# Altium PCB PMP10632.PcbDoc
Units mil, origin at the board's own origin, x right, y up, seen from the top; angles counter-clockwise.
Board outline 3700 x 2300 mil, 2 copper layers (Top Layer, Bottom Layer), stack 62 mil thick; 85 components, 32 nets, 206 pads, 12 vias.
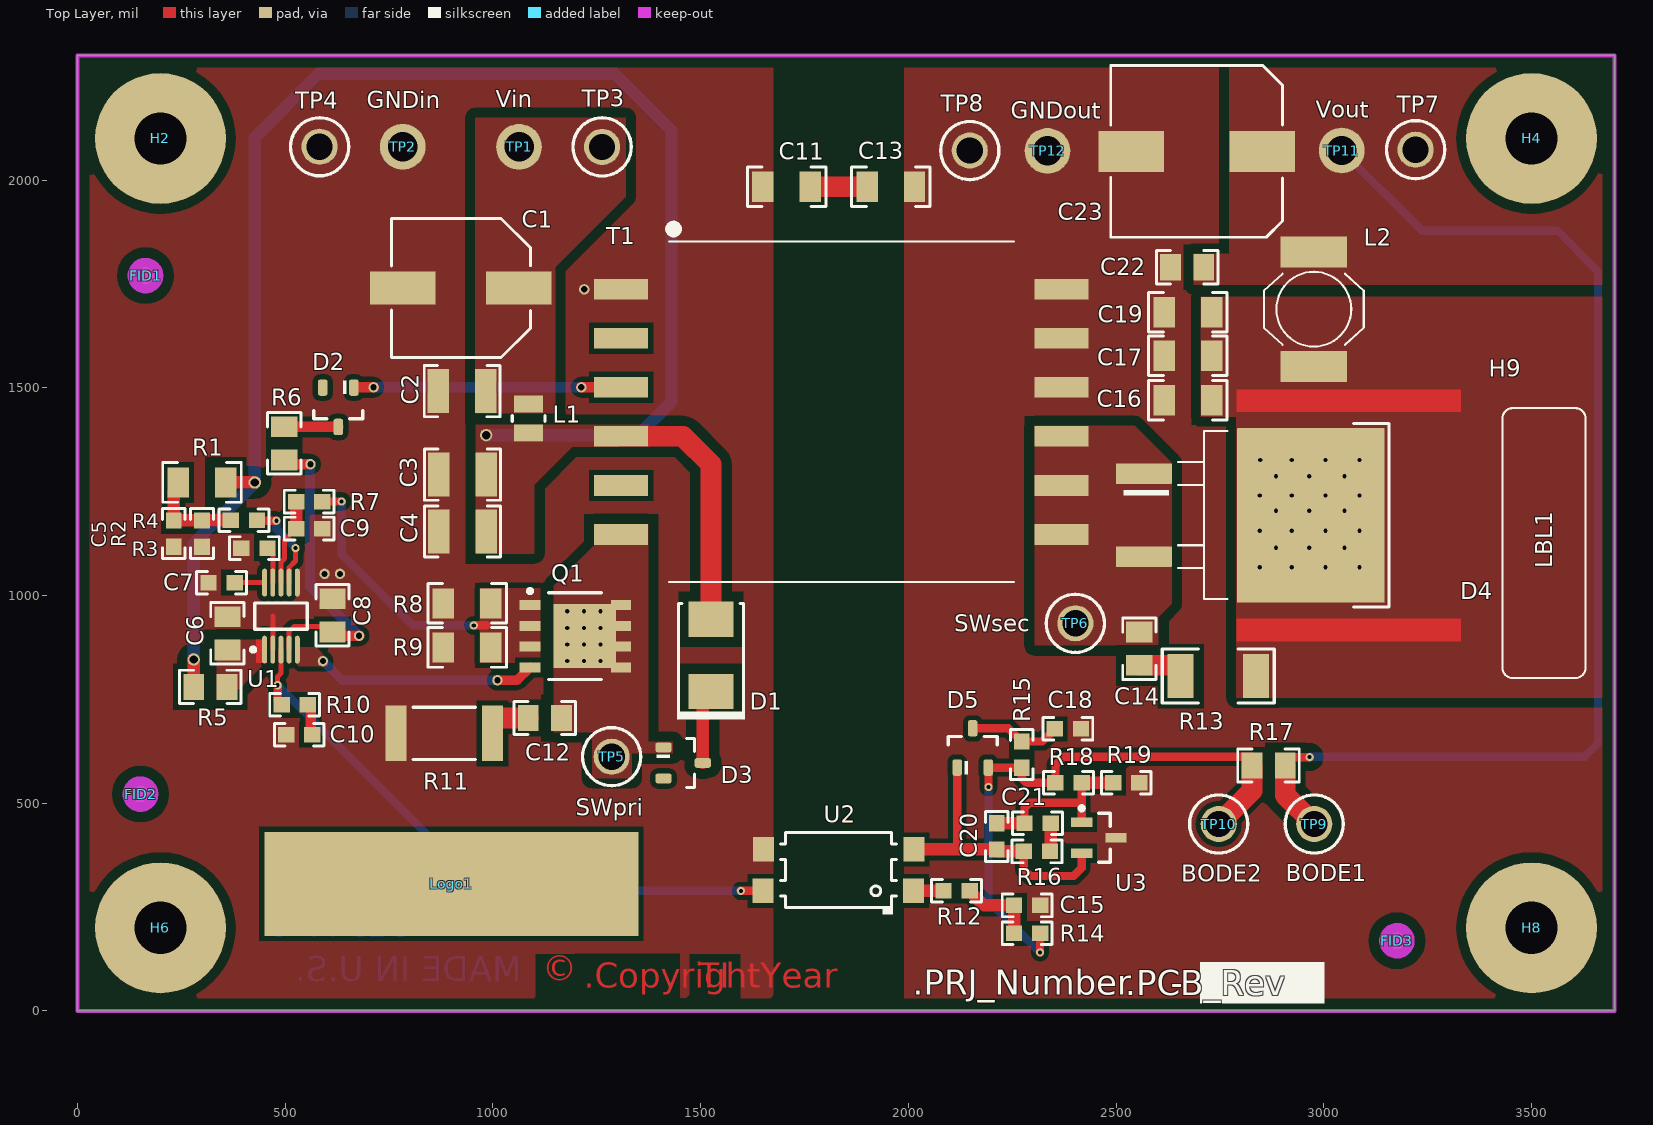
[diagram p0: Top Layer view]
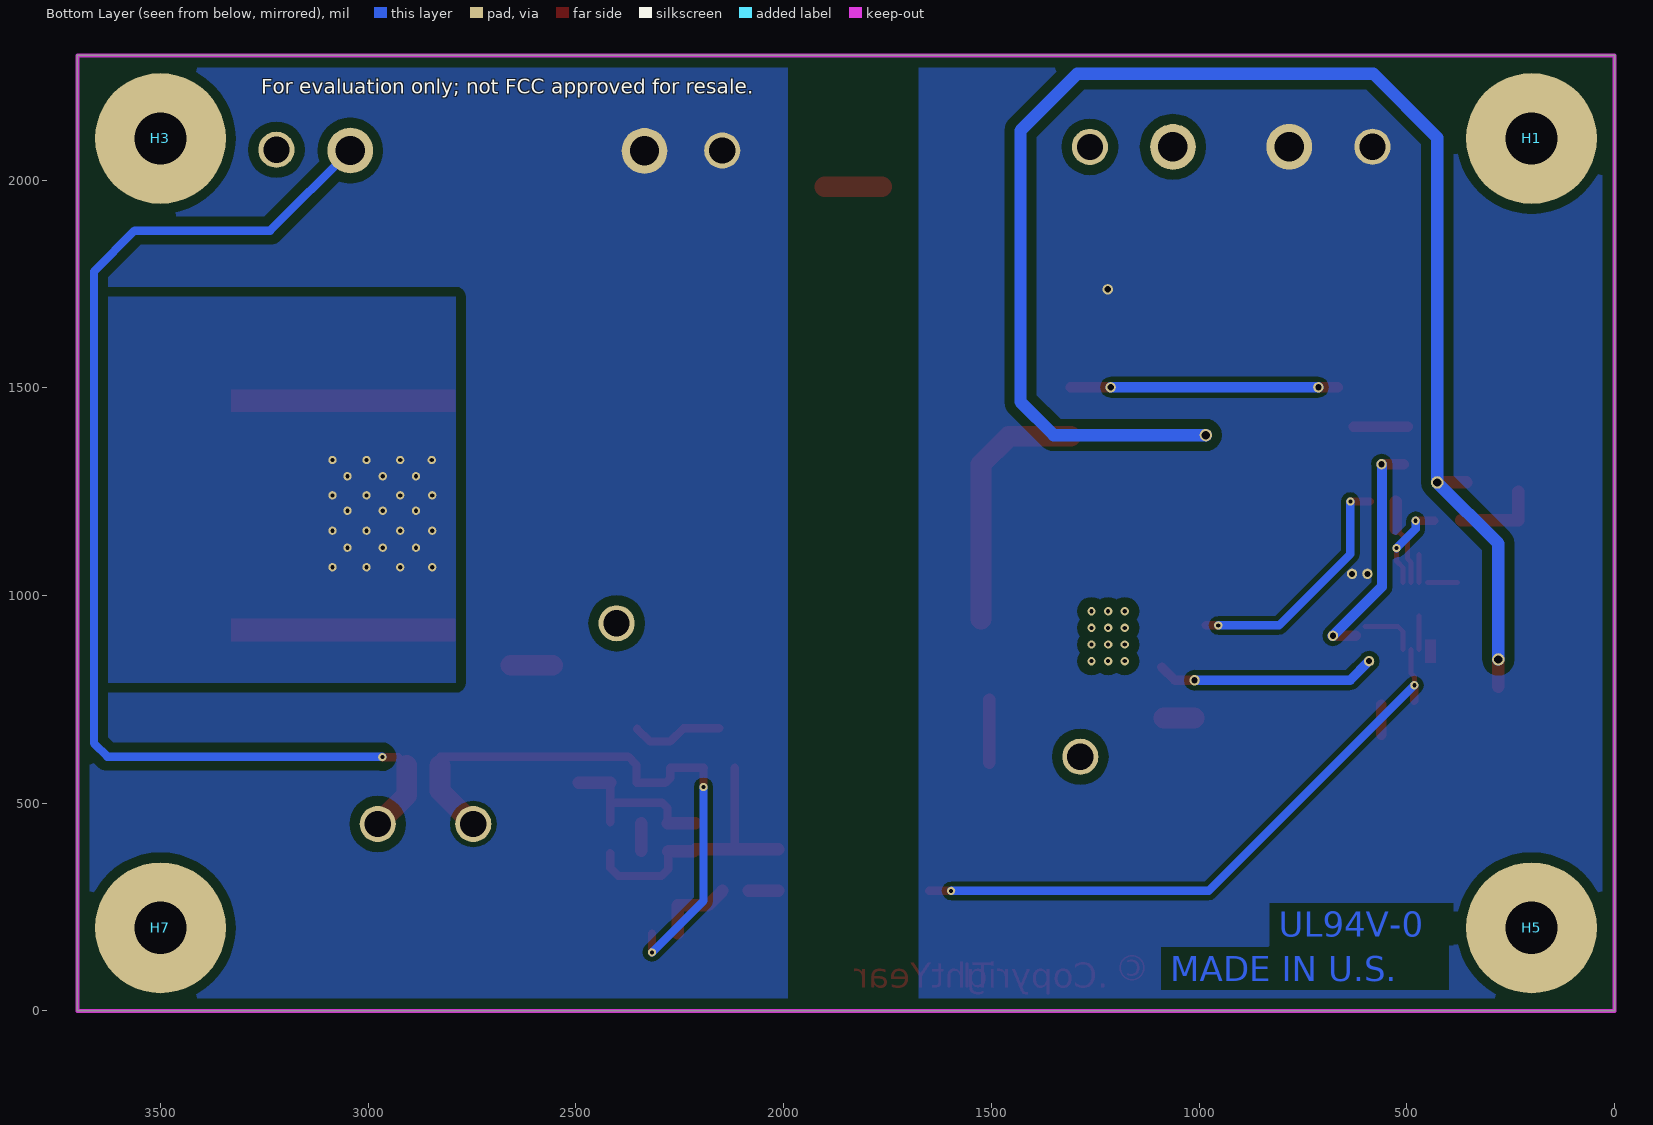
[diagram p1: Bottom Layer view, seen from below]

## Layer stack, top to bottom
Top Layer: signal copper 1.4
Dielectric: core 59.2, FR-4, Dk 4.8
Bottom Layer: signal copper 1.4

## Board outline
0,0 3700,0 3700,2300 0,2300

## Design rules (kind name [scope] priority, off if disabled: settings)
AcuteAngle [All] p1: minimum=4.50000000000000E+0001 checktracksonly=FALSE
AssemblyTestPointUsage [All] p1: valid=2
Clearance Clearance_PolygonandMountHole [InPolygon vs (InComponent('H1') OR InComponent('H2') OR InComponent('H3') OR InComponent('H4') OR InComponent('H5') OR InComponent('H6') OR InComponent('H7') OR InComponent('H8'))] p1: gap=24
Clearance Clearance_VinIC [InNet('VINIC')] p2: gap=24
Clearance Clearance_NoNet [InNet('No Net')] p3: gap=24
Clearance Clearance_SWpri [InNet('SWPRI')] p4: gap=24
Clearance Clearance_CLAMP [InNet('CLAMP')] p5: gap=24
Clearance Clearance_Vin [InNet('VIN')] p6: gap=24
Clearance Clearance_INPUT [InNet('INPUT')] p7: gap=24
Clearance Clearance_Vout [InNet('VOUT')] p8: gap=24
Clearance Clearance_VoutRect [InNet('VOUTRECT')] p9: gap=24
Clearance Clearance_SnubSec [InNet('SNUBSEC')] p10: gap=24
Clearance Clearance_SWsec [InNet('SWSEC')] p11: gap=24
Clearance Clearance_BoardEdge_MountingHoles [OnCopper and InComponentClass('Mounting Holes') vs IsKeepOut] p12: gap=30
Clearance Clearance_BoardEdge_Poly [OnCopper and InPoly vs IsKeepOut] p13: gap=25
Clearance Clearance_BoardEdge [OnCopper and Not InComponentClass('Logo') and not InComponentClass('FiducialMark') and not InRegion(1000,500,4000,800) and Not IsKeepout vs IsKeepOut] p14: gap=25
Clearance Clearance_Poly [InPolygon] p15: gap=12
Clearance [All] p16: gap=10
ComponentClearance ComponentClearance_Shunt [InComponentClass('Header') vs InComponentClass('Shunt')] p1: gap=0 collisioncheckmode=3 verticalgap=0 showdistances=FALSE
ComponentClearance ComponentClearance_MountingHoles_FiducialMarks [InComponentClass('Mounting Holes') vs InComponentClass('FiducialMark')] p2: gap=30 collisioncheckmode=3 verticalgap=10 showdistances=FALSE
ComponentClearance ComponentClearance_Logo [InComponentClass('Logo')] p3: gap=30 collisioncheckmode=3 verticalgap=10 showdistances=FALSE
ComponentClearance ComponentClearance_ScrewToNut [(HasFootprint('NY PMS 440 0025 PH')) vs (HasFootprint('Keystone_1902C'))] p4: gap=5 collisioncheckmode=3 verticalgap=10 showdistances=FALSE
ComponentClearance ComponentClearance_MountingHoles [InComponentClass('Mounting Holes')] p5: gap=30 collisioncheckmode=3 verticalgap=100000 showdistances=FALSE
ComponentClearance ComponentClearance_SmallPassives [HasFootprint('0201*') or HasFootprint('0402*') or HasFootprint('0508') or HasFootprint('0603*') or HasFootprint('0612') or HasFootprint('0805*') or HasFootprint('0815*') or HasFootprint('0830*') or HasFootprint('1206*') or HasFootprint('1210*') or HasFootprint('1808*') or HasFootprint('1812*') or HasFootprint('1825*') or HasFootprint('2010*') or HasFootprint('2220*') or HasFootprint('2225*') or HasFootprint('2512*') or HasFootprint('2728*') or HasFootprint('3518*') vs HasFootprint('0201*') or HasFootprint('0402*') or HasFootprint('0508') or HasFootprint('0603*') or HasFootprint('0612') or HasFootprint('0805*') or HasFootprint('0815*') or HasFootprint('0830*') or HasFootprint('1206*') or HasFootprint('1210*') or HasFootprint('1808*') or HasFootprint('1812*') or HasFootprint('1825*') or HasFootprint('2010*') or HasFootprint('2220*') or HasFootprint('2225*') or HasFootprint('2512*') or HasFootprint('2728*') or HasFootprint('3518*')] p6: gap=20 collisioncheckmode=3 verticalgap=10 showdistances=FALSE
ComponentClearance ComponentClearance_THtoSMT [IsThruComponent vs IsSMTComponent] p7: gap=30 collisioncheckmode=3 verticalgap=30 showdistances=FALSE
ComponentClearance ComponentClearance_THtoTH [IsThruComponent vs IsThruComponent] p8: gap=30 collisioncheckmode=3 verticalgap=30 showdistances=FALSE
ComponentClearance [All] p9: gap=15 collisioncheckmode=3 verticalgap=10 showdistances=FALSE
DiffPairsRouting [All] p1: maxlimit=100 minlimit=10 mostfreqgap=10 maxuncoupledlength=1000
FabricationTestPointUsage TestPointUsage [All] p1: valid=2 allowmultiple=FALSE
FabricationTestpoint Testpoint [All] p1: side=3 testpointundercomponent=TRUE minsize=40 maxsize=100 preferedsize=60 minholesize=0 maxholesize=40 preferedholesize=32 testpointgrid=1 allowsidetop=TRUE allowsidebottom=TRUE usegrid=TRUE gridtolerance=0.01
FanoutControl Fanout_LCC [IsLCC] p1: bgadir=Out bgaviamode=Centered fanoutstyle=Auto fanoutdirection=Alternating viagrid=1 // Fanout_LCC (Default Rule)
FanoutControl Fanout_BGA [IsBGA] p2: bgadir=Out bgaviamode=Centered fanoutstyle=Auto fanoutdirection=Alternating viagrid=1 // Fanout_BGA (Default Rule)
FanoutControl Fanout_Default [All] p4: bgadir=Out bgaviamode=Centered fanoutstyle=Auto fanoutdirection=Alternating viagrid=1 // Fanout_Default (Default Rule)
FanoutControl Fanout_Small [(CompPinCount < 5)] p5: bgadir=Out bgaviamode=Centered fanoutstyle=Auto fanoutdirection=OutThenIn viagrid=1 // Fanout_Small (Default Rule)
HoleSize [All] p1: absolutevalues=TRUE maxlimit=251 minlimit=10 maxpercent=80.000 minpercent=20.000
MinimumAnnularRing MinimumAnnularRing_ThermalPadVias [IsVia and InAnyComponent] p1: minimumring=5
MinimumAnnularRing [All] p2: minimumring=5
MinimumSolderMaskSliver MinimumSolderMaskSliver_Logo [InComponentClass('Logo') vs InComponentClass('Logo')] p1: minsoldermaskwidth=0.7
MinimumSolderMaskSliver [All] p2: minsoldermaskwidth=3.94
PlaneConnect [All] p1: planeconnectstyle=Direct reliefexpansion=10 reliefentries=4 reliefconductorwidth=10 reliefairgap=10
PolygonConnect [All] p1: connectstyle=Direct reliefconductorwidth=10 reliefentries=4 polygonreliefangle="90 Angle" airgapwidth=10
RoutingVias ThermalPadVias [IsVia and InAnyComponent] p1: holewidth=7.87 width=19.68 viastyle="Through Hole" minholewidth=10 minwidth=19.68 maxholewidth=12.99 maxwidth=23.62
RoutingVias [All] p2: holewidth=16 width=34 viastyle="Through Hole" minholewidth=10 minwidth=20 maxholewidth=40 maxwidth=65
SMDToCorner [All] p1: distance=30000
SilkToSilkClearance SilkToSilkClearance_Pb-FreeLogo [(HasFootprint('Pb-Free_Overlay_Medium') OR HasFootprint('Pb-Free_Overlay_Small')) vs (HasFootprint('Pb-Free_Overlay_Medium') OR HasFootprint('Pb-Free_Overlay_Small'))] p1: silktosilkclearance=0
SilkToSilkClearance [All] p2: silktosilkclearance=5
SilkscreenOverComponentPads [All] p1: minsilkscreentomaskgap=5
SolderMaskExpansion [All] p1: expansion=1.97
Width [All] p1: maxlimit=100 minlimit=6 preferedwidth=10 checkconnectedcopper=TRUE
14 further rules are at their usual default settings.

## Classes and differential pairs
component class "PMP10632 Schematic": C1 C2 C3 C4 C5 C6 C7 C8 C9 C10 C11 C12 C13 C14 C15 C16 C17 C18 C19 C20 C21 C22 C23 D1 D2 D3 D4 D5 H9 L1 L2 Q1 R1 R2 R3 R4 R5 R6 R7 R8 R9 R10 R11 R12 R13 R14 R15 R16 R17 R18 R19 T1 TP1 TP2 TP3 TP4 TP5 TP6 TP7 TP8 TP9 TP10 TP11 TP12 U1 U2 U3
component class "Mounting Holes": H2 H4 H6 H8
component class Logo: Logo1
component class PMP10632_Hardware_ANSI-B: FID1 FID2 FID3 H1 H2 H3 H4 H5 H6 H7 H8 LBL1 Logo1 Logo3 ZZ1 ZZ2 ZZ3 ZZ4
component class FiducialMark: FID1 FID2 FID3
component class AssemblyNote: ZZ1 ZZ2 ZZ3 ZZ4
component class Label: LBL1

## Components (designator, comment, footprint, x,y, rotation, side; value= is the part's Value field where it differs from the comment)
C1 "EEE-FK2A220P" SM_RADIAL_F 923,1740 r180 top
C2 "GRM32ER72A225KA35L" 1210 926,1492 r180 top
C3 "GRM32ER72A225KA35L" 1210 927,1291 r180 top
C4 "GRM32ER72A225KA35L" 1210 927,1154 r180 top
C5 "GRM188R71E103KA01D" 0603 232,1149 r270 top
C6 "C0805C104K1RACTU" 0805_HV 361,909 r90 top
C7 "GRM188R71E103KA01D" 0603 347,1031 r180 top
C8 "GRM21BR71C475KA73L" 0805_HV 614,952 r90 top
C9 "C0603C102J5GAC" 0603 558,1161 r0 top
C10 "GRM188R71H223KA01D" 0603 534,665 r180 top
C11 "VJ1206Y222KXGAT5Z" 1206 1707,1984 r180 top
C12 "GRM2165C2A471JA01D" 0805_HV 1125,705 r180 top
C13 "VJ1206Y222KXGAT5Z" 1206 1958,1984 r180 top
C14 "GRM2165C2A471JA01D" 0805_HV 2556,872 r270 top
C15 "GRM188R71E104KA01D" 0603 2286,254 r0 top
C16 "GRM31CR71E106KA12L" 1206 2673,1470 r180 top
C17 "GRM31CR71E106KA12L" 1206 2673,1577 r180 top
C18 "GRM188R71A105KA61D" 0603 2384,679 r0 top
C19 "GRM31CR71E106KA12L" 1206 2673,1682 r180 top
C20 "DNP" 0603 2212.56,420 r270 top
C21 "GRM188R71H223KA01D" 0603 2311,452 r180 top
C22 "GRM219R71E105KA88D" 0805_HV 2671,1790 r180 top
C23 "UCL1V391MNL1GS" SM_RADIAL_10BMM 2694,2069 r180 top
D1 "1SMB5936BT3G" SMB 1525,856 r90 top
D2 "BAS21-7-F" SOT-23 628,1453 r270 top
D3 "BAS21-7-F" SOT-23 1458,597 r0 top
D4 "MBRB2535CTLT4G" DDPAK 2813,1193 r0 top
D5 "BAT54S-7-F" SOT-23 2155,633 r90 top
FID1 "Fiducial" Fiducial10-20 164,1770 r0 top
FID2 "Fiducial" Fiducial10-20 152,522 r0 top
FID3 "Fiducial" Fiducial10-20 3176,169 r0 top
H1 "1902C" Keystone_1902C 200,2100 r180 bottom locked
H2 "NY PMS 440 0025 PH" "NY PMS 440 0025 PH" 200,2100 r0 top locked
H3 "1902C" Keystone_1902C 3500,2100 r180 bottom locked
H4 "NY PMS 440 0025 PH" "NY PMS 440 0025 PH" 3500,2100 r0 top locked
H5 "1902C" Keystone_1902C 200,200 r180 bottom locked
H6 "NY PMS 440 0025 PH" "NY PMS 440 0025 PH" 200,200 r0 top locked
H7 "1902C" Keystone_1902C 3500,200 r180 bottom locked
H8 "NY PMS 440 0025 PH" "NY PMS 440 0025 PH" 3500,200 r0 top locked
H9 "573300D00010G" HEATSINK_573300D00010G 3060,1193 r90 top
L1 "PFL2010-471MEB" PFL2010 1086,1426 r270 top
L2 "DO1813H-181MLB" DO1813H 2976,1689 r90 top
LBL1 "Size: 0.65\" x 0.20 \"" Label_650x200 3530,1126 r90 top
Logo1 "Texas Instruments" TI_Stacked_SolderMask_Small 900,306 r0 top
Logo3 "FCC disclaimer" FCC_disclaimer 3598.2,3140 r180 bottom
Q1 "SI7898DP-E3" PowerPAK_SO-8 1199,902 r0 top
R1 "CRCW120661K9FKEA" 1206 300,1272 r0 top
R2 "CRCW06032K87FKEA" 0603 300,1149 r90 top
R3 "CRCW060312K4FKEA" 0603 426,1114 r0 top
R4 "CRCW06031K00FKEA" 0603 401,1181 r0 top
R5 "CRCW080510R0JNEA" 0805_HV 320,780 r180 top
R6 "CRCW080520R0JNEA" 0805_HV 498,1366 r270 top
R7 "CRCW0603100RFKEA" 0603 558,1226 r0 top
R8 "ERJ-8RQFR47V" 1206 938,981 r0 top
R9 "ERJ-8RQFR47V" 1206 938,875 r0 top
R10 "CRCW0603220RJNEA" 0603 523,737 r180 top
R11 "CRCW251210R0JNEG" 2512 883,668 r0 top
R12 "CRCW0603680RJNEA" 0603 2116,289 r0 top
R13 "CRCW201010R0FKEF" 2010 2746,806 r180 top
R14 "CRCW060310R0FKEA" 0603 2286,187 r180 top
R15 "CRCW060310K0JNEA" 0603 2273,617 r270 top
R16 "CRCW06031R00JNEA" 0603 2309.56,384 r180 top
R17 "CRCW080510R0JNEA" 0805_HV 2867,591 r0 top
R18 "CRCW060314K7FKEA" 0603 2385.56,549 r180 top
R19 "CRCW06038K87FKEA" 0603 2524.56,549 r180 top
T1 "B0695-A" B0695-A 1839,1442 r0 top
TP1 "Vin" Keystone1593-2 1063.05,2079.68 r270 top
TP2 "GNDin" Keystone1593-2 783,2079.97 r270 top
TP3 "" Keystone5010 1263.05,2079.68 r0 top
TP4 "" Keystone5011 583,2079.97 r0 top
TP5 "SWpri" Keystone5012 1286,612 r0 top
TP6 "SWsec" Keystone5012 2402,933 r0 top
TP7 "" Keystone5010 3221,2073 r0 top
TP8 "" Keystone5011 2148,2071 r0 top
TP9 "BODE1" Keystone5012 2977,450 r0 top
TP10 "BODE2" Keystone5012 2747,450 r0 top
TP11 "Vout" Keystone1593-2 3043,2071 r0 top
TP12 "GNDout" Keystone1593-2 2335,2070 r0 top
U1 "LM5020MM-1/NOPB" MUB10A_N 490,950.5 r90 top
U2 "FOD817ASD" N04C 1832,339 r180 top
U3 "LMV431AIMF" MF03A_N 2458.56,417 r0 top
ZZ1 "This Assembly Note is for PCB labels only" AssemblyNoteLabel -415,3738 r0 top
ZZ2 "These assemblies are ESD sensitive, ESD precautions shall be observed." AssemblyNote -415,3629.11 r0 top
ZZ3 "These assemblies must be clean and free from flux and all contaminants. Use of no clean flux is not acceptable." AssemblyNote -415,3540.56 r0 top
ZZ4 "These assemblies must comply with workmanship standards IPC-A-610 Class 2, unless otherwise specified." AssemblyNote -415,3452 r0 top

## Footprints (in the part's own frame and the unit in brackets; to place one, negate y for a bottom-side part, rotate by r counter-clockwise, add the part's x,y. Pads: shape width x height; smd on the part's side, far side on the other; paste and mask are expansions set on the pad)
0603 [mm] "0603 from SM-752 data"
  rect 1x0.95 smd: 1(-0.8,0) 2(0.8,0)
  silkscreen extent -1.52,-0.69 1.52,0.69, body extent -0.87,-0.47 0.87,0.47, height 0.85
0805_HV [mil] "0805 with 30mil clearance between pads"
  rect 50x63 smd: 1(-40,0) 2(40,0)
  silkscreen extent -74,-40 74,40, body extent -43,-29 43,29, height 43
1206 [mm] "1206 from SM-752 data"
  rect 1.3x1.85 smd: 1(-1.45,0) 2(1.45,0)
  silkscreen extent -2.4,-1.21 2.4,1.21, body extent -1.7,-0.9 1.7,0.9, height 1.35
1210 [mm] "1210 from SM-752 data"
  rect 1.3x2.7 smd: 1(-1.45,0) 2(1.45,0)
  silkscreen extent -2.32,-1.57 2.32,1.57, body extent -1.7,-1.35 1.7,1.35, height 1.35
2010 [mm] "Chip Capacitor, Body 5.08x2.54mm, IPC Medium Density"
  rect 1.6x2.7 smd: 1(-2.3,0) 2(2.3,0)
  silkscreen extent -3.42,-1.65 3.42,1.65, body extent -2.73,-1.45 2.73,1.45, height 1.66
2512 [mm] "Chip Resistor, Body 6.3x3.2mm, IPC Medium Density"
  rect 1.3x3.4 smd: 1(-2.95,0) 2(2.95,0)
  silkscreen extent -1.9,-1.6 1.9,1.6, body extent -3.22,-1.67 3.22,1.67, height 0.71
AssemblyNote [mil] "Assembly Note"
AssemblyNoteLabel [mil] "Assembly Note for PCB Labels"
B0695-A [mil] "1:0.23 and 1:0.69 Transformer"
  rect 130x50 smd: 1(-530,295) 2(-530,177) 3(-530,59) 4(-530,-59) 5(-530,-177) 6(-530,-295) 7(530,-295) 8(530,-177) 9(530,-59) 10(530,59) 11(530,177) 12(530,295)
  silkscreen extent -415,-410 415,450
DDPAK [mil] "D2-PAK, 3-Pads, Body 9.7x10.4mm (max), TO-263AB, using Vishay Silionix recommended pad sizes"
  rrect8% 135x49.49 smd: 1(-246.06,100) 3(-246.06,-100)
  rrect1% 355x420 smd paste-181.1: 4(155.51,0)
  silkscreen extent -295,-220 344,220, body extent -295,-202 324,202, height 180
DO1813H [mil] "Coilcraft DO1813H recommended land pattern"
  rect 75x160 smd: 1(-137.5,0) 2(137.5,0)
  silkscreen extent -90,-120 90,120, body extent -175,-120 175,120, height 197
FCC_disclaimer [mil]
Fiducial10-20 [mm]
  round 1 smd mask+0.5: 1(0,0)
  Top Layer keep-out circle w1.178: c0,0 r0.5
HEATSINK_573300D00010G [mil] "Aavid"
  Top Layer region: -248.03,269.68 -303.15,269.68 -303.15,-269.69 -248.03,-269.69
  Top Layer region: 248.03,-269.69 303.15,-269.69 303.15,269.68 248.03,269.68
  body extent -515,-250 515,250, height 400
Keystone1593-2 [mm] "Keystone Dual Turret"
  round 2.8 hole 1.8: 1(0,0)
  body extent -1.17,-1.19 1.21,1.19, height 4
Keystone5010 [mil] "Keystone Multipurpose loops"
  round 87 hole 63: 1(0,0)
  silkscreen extent -70,-70 70,70, body extent -63,-63 63,62, height 319
Keystone5011 [mil] "Keystone Multipurpose loops"
  round 87 hole 63: 1(0,0)
  silkscreen extent -70,-70 70,70, body extent -63,-63 63,62, height 319
Keystone5012 [mil] "Keystone Multipurpose loops"
  round 87 hole 63: 1(0,0)
  silkscreen extent -70,-70 70,70, body extent -63,-63 63,62, height 319
Keystone_1902C [mil] "Hex Standoff, 4-40 threaded, nylon"
  body extent -145,-126 146,126, height 501
Label_650x200 [mil] "Thermal Transfer Label"
  silkscreen extent -325,-100 325,100, body extent -326,-101 326,101, height 1
MF03A_N [mm] "SOT23, 3-Leads, Body 2.9x1.3mm, Pitch 0.95mm, Lead Span 2.4mm, IPC Medium Density"
  rect 1.3x0.6 smd: 1(-1.05,0.95) 2(-1.05,-0.95) 3(1.05,0)
  silkscreen extent -1.17,-1.5 0.7,1.92, body extent -0.7,-1.5 0.7,1.5, height 1.12
MUB10A_N [mm] "TSSOP, 10-Leads, Body 3x3mm, Pitch 0.5mm, IPC Medium Density"
  oval 1.7x0.3 smd: 1(-2.05,1) 2(-2.05,0.5) 3(-2.05,0) 4(-2.05,-0.5) 5(-2.05,-1) 6(2.05,-1) 7(2.05,-0.5) 8(2.05,0) 9(2.05,0.5) 10(2.05,1)
  silkscreen extent -2.17,-1.6 0.8,1.82, body extent -1.6,-1.6 1.6,1.6, height 1.09
N04C [mm] "FAIRCHILD"
  rect 1.3x1.5 smd mask+0.065: 1(-4.587,1.27) 2(-4.612,-1.27) 3(4.588,-1.27) 4(4.613,1.27)
  silkscreen extent -3.56,-2.3 3.56,2.72, body extent -5.08,-2.3 5.08,2.3, height 3.87
"NY PMS 440 0025 PH" [mm] "4-40 nylon screw and mounting hole"
  round 8 hole 3.2: 1(0,0)
  body extent -3.3,-3.3 3.3,3.3, height 2.69
PFL2010 [mm] "SMD, 2-Leads, Body 2.2x1.45mm"
  rect 1.02x1.78 smd: 1(-0.89,0) 2(0.89,0)
  silkscreen extent -0.18,-1 0.18,1, body extent -1.1,-0.72 1.1,0.73, height 0.99
PowerPAK_SO-8 [mil] "Vishay PowerPAK SO-8, Body 5.3x6.0mm (max), Pitch 1.27mm, IPC Medium Density"
  rect 50x24 smd mask+2.99: 1(-109.5,75) 2(-109.5,25) 3(-109.5,-25) 4(-109.5,-75)
  rect 48x24 smd mask+2.99: 5(109.5,-75) 8(109.5,75)
  rect 48x24 smd paste-12 mask+2.99: 6(109.5,-25) 7(109.5,25)
  rect 150x154 smd paste-75 mask+2.99: 9(22.5,0)
  silkscreen extent -114,-104 62,113, body extent -121,-102 121,102, height 43
SM_RADIAL_10BMM [mm] "Nichicon 10x10"
  rect 4x2.5 smd: 1(-4,0) 2(4,0)
  silkscreen extent -5.25,-5.25 5.25,5.25, body extent -5.26,-5.26 5.26,5.26, height 10.5
SM_RADIAL_F [mm] "8 x 10.2mm:  Panasonic F"
  rect 4x2 smd: 1(-3.55,0) 2(3.55,0)
  silkscreen extent -4.25,-4.25 4.25,4.25, body extent -4.26,-4.26 4.26,4.26, height 10.5
SMB [mil] "Molded Diode, 2-Leads, Body 5.4x3.6mm, IPC Medium Density, based on OnSemi component dimensions"
  rect 85x107.99 smd: 1(-87.01,0) 2(87.01,0)
  silkscreen extent -155,-82 125,82, body extent -106,-71 106,71, height 91
SOT-23 [mm] "SOT23, 3-Leads, Body 2.9x1.3mm, Pitch 0.95mm, Lead Span 2.5mm, IPC Medium Density"
  rrect50% 1x0.6 smd: 1(-1.2,0.95) 2(-1.2,-0.95) 3(1.2,0)
  silkscreen extent -1.63,-1.5 0.7,1.5, body extent -1.16,-1.45 1.21,1.45, height 1
TI_Stacked_SolderMask_Small [mil]
  rect 900x250 smd paste-125 mask-125: 0(0,0)

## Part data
C1: "CAP, AL, 22 µF, 100 V, +/- 20%, 1.3 ohm, SMD"
C2 C3 C4: "CAP, CERM, 2.2 µF, 100 V, +/- 10%, X7R, 1210"
C5 C7: "CAP, CERM, 0.01 µF, 25 V, +/- 10%, X7R, 0603"
C6: "CAP, CERM, 0.1 µF, 100 V, +/- 10%, X7R, 0805"
C8: "CAP, CERM, 4.7 µF, 16 V, +/- 10%, X7R, 0805"
C9: "CAP, CERM, 1000 pF, 50 V, +/- 5%, C0G/NP0, 0603"
C10 C21: "CAP, CERM, 0.022 µF, 50 V, +/- 10%, X7R, 0603"
C11 C13: "CAP, CERM, 2200 pF, 1000 V, +/- 10%, X7R, 1206"
C12 C14: "CAP, CERM, 470 pF, 100 V, +/- 5%, C0G/NP0, 0805"
C15: "CAP, CERM, 0.1 µF, 25 V, +/- 10%, X7R, 0603"
C16 C17 C19: "CAP, CERM, 10 µF, 25 V, +/- 10%, X7R, 1206"
C18: "CAP, CERM, 1 µF, 10 V, +/- 10%, X7R, 0603"
C20: library part GRM1885C1H101JA01D, "CAP, CERM, 100 pF, 50 V, +/- 5%, C0G/NP0, 0603"
C22: "CAP, CERM, 1 µF, 25 V, +/- 10%, X7R, 0805"
C23: "CAP, AL, 390 µF, 35 V, +/- 20%, 0.08 ohm, SMD"
D1: "Diode, Zener, 30 V, 550 mW, SMB"
D2 D3: "Diode, Switching, 200 V, 0.2 A, SOT-23"
D4: "Diode, Schottky, 35 V, 25 A, DDPAK"
D5: "Diode, Schottky, 30 V, 0.2 A, SOT-23"
FID1 FID2 FID3: "Fiducial mark.  There is nothing to buy or mount."
H1 H3 H5 H7: "Standoff, Hex, 0.5\"L #4-40 Nylon"
H2 H4 H6 H8: "Machine Screw, Round, #4-40 x 1/4, Nylon, Philips panhead"
H9: "Heatsink, DDPAK/TO-263, SMT"
L1: "Inductor, Shielded, Composite, 470 nH, 1.8 A, 0.06 ohm, SMD"
L2: "Inductor, Drum Core, Ferrite, 180 nH, 10 A, 0.003 ohm, SMD"
LBL1: library part THT-14-423-10, "Thermal Transfer Printable Labels, 0.650\" W x 0.200\" H - 10,000 per roll"
Logo1: library part TI_Logo, "Texas Instrument Corporate Signature"
Logo3: library part FCC_disclaimer, "FCC_disclaimer"
Q1: "MOSFET, N-CH, 150 V, 3 A, PowerPAK SO-8"
R1: "RES, 61.9 k, 1%, 0.25 W, 1206"
R2: "RES, 2.87 k, 1%, 0.1 W, 0603"
R3: "RES, 12.4 k, 1%, 0.1 W, 0603"
R4: "RES, 1.00 k, 1%, 0.1 W, 0603"
R5 R17: "RES, 10, 5%, 0.125 W, 0805"
R6: "RES, 20, 5%, 0.125 W, 0805"
R7: "RES, 100, 1%, 0.1 W, 0603"
R8 R9: "RES, 0.47, 1%, 0.25 W, 1206"
R10: "RES, 220, 5%, 0.1 W, 0603"
R11: "RES, 10, 5%, 1 W, 2512"
R12: "RES, 680, 5%, 0.1 W, 0603"
R13: "RES, 10.0, 1%, 0.75 W, 2010"
R14: "RES, 10.0, 1%, 0.1 W, 0603"
R15: "RES, 10 k, 5%, 0.1 W, 0603"
R16: "RES, 1.0, 5%, 0.1 W, 0603"
R18: "RES, 14.7 k, 1%, 0.1 W, 0603"
R19: "RES, 8.87 k, 1%, 0.1 W, 0603"
T1: "Pri:Sec = 1:0.23; Pri:Bias = 1:0.69 Transformer 1500Vrms Isolation"
TP1 TP2 TP11 TP12: library part 1593-2, "Terminal, Turret, TH, Double"
TP3 TP7: library part 5010, "Test Point, Multipurpose, Red, TH"
TP4 TP8: library part 5011, "Test Point, Multipurpose, Black, TH"
TP5 TP6 TP9 TP10: library part 5012, "Test Point, Multipurpose, White, TH"
U1: "100V Current Mode PWM Controller, 10-pin MSOP, Pb-Free"
U2: "IC, Optocoupler, 5000V, 80-160% CTR"
U3: "Low-Voltage (1.24V) Adjustable Precision Shunt Regulator, 3-pin SOT-23"
ZZ1: library part AssemblyNoteLabel
ZZ2 ZZ3 ZZ4: library part AssemblyNote

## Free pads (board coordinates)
  round 30 hole 20: 0(280,846) 0(427,1272) 0(984,1386)
  round 20 hole 10: 0(479,1180) 0(482,784) 0(525,1114) 0(636,1226) 0(1597,289) 0(2193,539) 0(2317,141) 0(2846,1068) 0(2846,1156) 0(2846,1241) 0(2847,1326) 0(2885,1115) 0(2885,1204) 0(2885,1287) 0(2923,1068) 0(2923,1156) 0(2923,1241) 0(2923,1326) 0(2965,1115) 0(2965,1204) 0(2965,1287) 0(2966,611) 0(3004,1068) 0(3004,1156) 0(3004,1241) 0(3004,1326) 0(3050,1115) 0(3050,1204) 0(3050,1287) 0(3086,1068) 0(3086,1156) 0(3086,1241) 0(3086,1326) 1(954,928)
  round 25 hole 15: 0(561,1316) 0(595,1052) 0(678,903) 0(713,1501) 0(1011,796) 0(1213,1501) 0(1220,1737) 1(591,842) 1(632,1052)

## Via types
v1: diameter 20, hole 10, Top Layer to Bottom Layer, tented top, 12 vias

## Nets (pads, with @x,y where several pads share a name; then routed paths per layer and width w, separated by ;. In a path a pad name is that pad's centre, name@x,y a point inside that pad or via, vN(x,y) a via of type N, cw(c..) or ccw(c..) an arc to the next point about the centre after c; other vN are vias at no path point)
CLAMP: D1.1 D3.3 | length 152.2
  Top Layer w30: D3.3 D1.1@1505.24,749.24
COMPIC: pad.0@482,784 pad.0@1597,289 R10.2 U1.3 U2.4 | length 1500
  Top Layer w12: pad.0@482,784 482,805 490,813 U1.3
  Top Layer w20: R10.2@482,746.5 pad.0@482,784 ; pad.0@1597,289 U2.4
  Bottom Layer w20: pad.0@482,784 977,289 pad.0@1597,289
CS: C9.1 R7.1 U1.8 | length 209.9
  Top Layer w12: U1.8 490,1080 499,1089 499,1133.5 C9.1
  Top Layer w30: C9.1 R7.1
FBSEC: C20.1 C21.2 R18.1 R19.2 U3.1 | length 416.3
  Top Layer w20: C21.2 2279.5,488.5 2292,501 2417.22,501 ; U3.1 2417.22,501 ; R18.1@2417.22,548.83 2417.22,501
  Top Layer w30: C20.1 C21.2@2279,451.5 ; R18.1 R19.2
GND: C1.2 C2.2 C3.2 C4.2 C5.2 C6.2 C7.2 C8.2 C9.2 C10.2 C11.2 pad.0@595,1052 pad.0@1220,1737 pad.1@632,1052 R2.1 R3.1 R8.1 R9.1 R11.1 T1.1 TP2.1 TP4.1 U1.2 U1.6 U2.3 | length 80.7
  Top Layer w12: U1.2 470.31,950.5
INPUT: C1.1 C2.1 L1.1 TP1.1 TP3.1
ISO: C11.1 C13.2 | length 136.9
  Top Layer w50: C11.1@1764,1984 C13.2
"ISO GND": C13.1 C15.2 C16.2 C17.2 C18.2 C19.2 C22.2 C23.2 R19.1 T1.10 T1.11 T1.12 TP8.1 TP12.1 U3.3
LEDA: R12.1 U2.1 | length 71.9
  Top Layer w30: U2.1 R12.1
LEDK: C20.2 D5.1 R16.2 U2.2 U3.2 | length 688.4
  Top Layer w20: 2117.6,389 D5.1 ; R16.2 2278.06,340.94 2294,325 2398,325 2417.22,344.22 U3.2
  Top Layer w30: U2.2 2117.6,389 C20.2@2212.06,389 ; C20.2@2217.06,384 R16.2
NetC10_1: C10.1 R10.1 | length 72
  Top Layer w25: C10.1@561.5,665 R10.1@561.5,737
NetC15_1: C15.1 R12.2 R14.2 | length 188.5
  Top Layer w30: R12.2 2182.5,254 C15.1 R14.2
NetC21_1: C21.1 R16.1 | length 66.6
  Top Layer w30: R16.1@2342.5,385.44 C21.1
NetD5_2: D5.2 pad.0@2193,539 pad.0@2317,141 R14.1 R15.2 R17.1 R18.2 TP10.1 | length 1430.7
  Top Layer w20: D5.2 2272.75,585.76 2272.75,561.25 2285,549 R18.2 2354.06,592.06 2374,612 R17.1@2827,612 ; pad.0@2193,539 D5.2@2193,585.16 ; pad.0@2317,141 R14.1@2317,186.5
  Top Layer w50: TP10.1 2827,530 R17.1
  Bottom Layer w20: pad.0@2193,539 2193,265 pad.0@2317,141
OUT: pad.0@1011,796 pad.1@591,842 Q1.4 U1.5 | length 530.4
  Top Layer w23: pad.0@1011,796 1058.5,796 Q1.4
  Bottom Layer w23: pad.1@591,842 637,796 pad.0@1011,796
RSENSE: pad.0@636,1226 pad.1@954,928 Q1.1 Q1.2 Q1.3 R7.2 R8.2 R9.2 | length 591.7
  Top Layer w20: R7.2 pad.0@636,1226 ; pad.1@954,928 984,928
  Bottom Layer w20: pad.0@636,1226 636,1100 808,928 pad.1@954,928
RT: R3.2 U1.9 | length 68
  Top Layer w12: U1.9 R3.2@470.31,1099.18
SNUBPRI: C12.2 R11.2 | length 73
  Top Layer w50: R11.2@1012,705 C12.2
SNUBSEC: C14.2 R13.2 | length 100.4
  Top Layer w50: C14.2 R13.2@2656.45,832
SSIC: C7.1 U1.10 | length 71.9
  Top Layer w12: C7.1 U1.10@450.43,1031
SSSEC: C18.1 D5.3 R15.1 | length 223.3
  Top Layer w20: D5.3 2241.25,680.24 R15.1 2322,648.5 C18.1
SWBIAS: D2.1 pad.0@713,1501 pad.0@1213,1501 T1.3 | length 642.8
  Top Layer w25: D2.1@666.16,1501 pad.0@713,1501 ; pad.0@1213,1501 T1.3
  Bottom Layer w25: pad.0@713,1501 pad.0@1213,1501
SWPRI: C12.1 D3.1 Q1.5 Q1.6 Q1.7 Q1.8 Q1.9 T1.6 TP5.1
  other v1: 1179,842 1219,842 1259,842 1179,882 1219,882 1259,882 1179,922 1219,922 1259,922 1179,962 1219,962 1259,962
SWSEC: C14.1 D4.1 D4.3 T1.7 T1.8 T1.9 TP6.1
UVLO: C5.1 R1.1 R2.2 R4.1 | length 206.5
  Top Layer w30: C5.1 R1.1@232,1250 ; C5.1@232.5,1181 R4.1
UVLOIC: pad.0@479,1180 pad.0@525,1114 R4.2 U1.7 | length 219.7
  Top Layer w12: U1.7 509.68,1067.68 525,1083 pad.0@525,1114
  Top Layer w20: R4.2@433.5,1180 pad.0@479,1180
  Bottom Layer w20: pad.0@479,1180 479,1160 pad.0@525,1114
VBIAS: D2.3 R6.1 | length 129.8
  Top Layer w25: R6.1@498.24,1405.76 D2.3
VCC: C8.1 pad.0@561,1316 pad.0@678,903 R6.2 U1.4 | length 710.2
  Top Layer w12: U1.4 509.68,913.68 521,925 C8.1@601,925
  Top Layer w25: R6.2@508,1316 pad.0@561,1316 ; C8.1@623,903 pad.0@678,903
  Bottom Layer w25: pad.0@561,1316 560,1315 560,1021 pad.0@678,903
VIN: C3.1 C4.1 D1.2 L1.2 pad.0@280,846 pad.0@427,1272 pad.0@984,1386 R1.2 R5.2 T1.4 | length 4325.2
  Top Layer w30: R5.2 pad.0@280,846 ; R1.2 pad.0@427,1272
  Top Layer w50: T1.4 1458,1383 1525,1316 D1.2
  Bottom Layer w30: pad.0@280,846 280,1125 427,1272 427,2102 581,2256 1293,2256 1430,2119 1430,1466 1350,1386 pad.0@984,1386
VINIC: C6.1 R5.1 U1.1
VOUT: C22.1 C23.1 L2.2 pad.0@2966,611 R17.2 TP7.1 TP9.1 TP11.1 | length 2789.8
  Top Layer w20: R17.2@2927,611 pad.0@2966,611
  Top Layer w50: R17.2 2907,520 TP9.1
  Bottom Layer w20: pad.0@2966,612 3628,612 3660,644 3660,1780 3562,1878 3236,1878 TP11.1
VOUTRECT: C16.1 C17.1 C19.1 D4.4 L2.1 pad.0@2846,1068 pad.0@2846,1156 pad.0@2846,1241 pad.0@2847,1326 pad.0@2885,1115 pad.0@2885,1204 pad.0@2885,1287 pad.0@2923,1068 pad.0@2923,1156 pad.0@2923,1241 pad.0@2923,1326 pad.0@2965,1115 pad.0@2965,1204 pad.0@2965,1287 pad.0@3004,1068 pad.0@3004,1156 pad.0@3004,1241 pad.0@3004,1326 pad.0@3050,1115 pad.0@3050,1204 pad.0@3050,1287 pad.0@3086,1068 pad.0@3086,1156 pad.0@3086,1241 pad.0@3086,1326 R13.1
pads on no net: D2.2 D3.2 FID1.1 FID2.1 FID3.1 H2.1 H4.1 H6.1 H8.1 Logo1.0 T1.2 T1.5

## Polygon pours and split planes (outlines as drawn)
VOUTRECT on Bottom Layer "Bottom Layer-VoutRect" (solid, remove dead copper, pour order 14): 2789,1719 2798,1719 3700,1719 3700,1709 3700,790 3696,790 2789,790 2789,795 2789,1719
"ISO GND" on Bottom Layer "Bottom Layer-ISO GND" (solid, remove dead copper, pour order 16): 1990,35 1990,44 1990,2300 2002,2300 3700,2300 3700,2289 3700,0 3688,0 1990,0 1990,35
GND on Bottom Layer "Bottom Layer-GND" (solid, remove dead copper, pour order 34): 0,0 0,3 0,2300 2,2300 114,2300 1675,2300 1675,2283 1675,0 1665,0 0,0
VOUT on Top Layer "Top Layer-Vout" (solid, remove dead copper, pour order 6): 3700,1748 3700,2300 2772,2300 2772,1823 2687,1823 2687,1748
SWSEC on Top Layer "Top Layer-SWsec" (solid, remove dead copper, pour order 2): 2304,1408 2545,1408 2634,1319 2634,980 2602,948 2602,879 2505,880 2304,880
VOUTRECT on Top Layer "Top Layer-VoutRect" (solid, remove dead copper, pour order 4): 2704,1719 3700,1719 3700,754 2789,754 2789,1430 2704,1430
OUT on Top Layer "Top Layer-Out" (solid, remove dead copper, pour order 30): 603,830 524,830 524,875 575,875 603,847
VINIC on Top Layer "Top Layer-VinIC" (solid, remove dead copper, pour order 28): 335,894 456,894 456,842 385,771 385,749 335,749
VIN on Top Layer "Top Layer-Vin" (solid, remove dead copper, pour order 26): 959,1411 1376,1411 1376,1358 1191,1358 1100,1267 1100,1101 959,1101
INPUT on Top Layer "Top Layer-Input" (solid, remove dead copper, pour order 24): 958,1439 958,1448 958,1518 958,2150 969,2150 1320,2150 1320,2132 1320,1960 1150,1790 1150,1776 1150,1439 1144,1439 958,1439
"ISO GND" on Top Layer "Top Layer-ISO GND" (solid, remove dead copper, pour order 10): 1990,440 1990,451 1990,2300 2002,2300 3700,2300 3700,2280 3700,0 3684,0 1990,0 1990,15 1990,440
SWPRI on Top Layer "Top Layer-SWpri" (solid, remove dead copper, pour order 20): 1147,1024 1244,1121 1244,1172 1374,1172 1374,648 1433,648 1433,620 1334,620 1334,560 1239,560 1239,671 1147,671
RSENSE on Top Layer "Top Layer-Rsense" (solid, remove dead copper, pour order 18): 969,1015 969,1018 979,1018 1114,1018 1114,1015 1114,989 1114,986 1114,945 1114,880 1114,857 1114,838 1086,838 1027,838 971,838 969,838 969,847 969,1015
GND on Top Layer "Top Layer-GND" (solid, remove dead copper, pour order 32): 0,0 0,3 0,2300 7,2300 1675,2300 1675,2283 1675,0 1668,0 0,0

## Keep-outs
Keep-Out Layer:
  the board outline again, w10
  text ".Layer_Name" at -23,-1058.49 h60

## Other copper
Top Layer:
  rectangle net VINIC: 430,837 456,894
  text ".CopyrightYear" at 1219,56 h60
  text "TI" at 1495,56 h60
  text "©" at 1119,52 h105
  text ".Layer_Name" at -23,-1058.49 h60
Bottom Layer:
  text "UL94V-0" at 809,179 h60
  text "MADE IN U.S." at 1070,72 h60
  text ".Layer_Name" at -23,-1058.49 h60

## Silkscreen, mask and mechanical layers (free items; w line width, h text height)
Top Overlay:
  region: 3002,118 2702,118 2702,18 3002,18
  text ".PRJ_Number" at 2011,39 h60
  text ".PCB_Rev" at 2522,38.01 h60
  text "-" at 2632,38.01 h60
  text ".Layer_Name" at -23,-1058.49 h60
Bottom Overlay:
  text ".Layer_Name" at -23,-1058.49 h60
Top Paste:
  text ".Layer_Name" at -23,-1058.49 h60
Bottom Paste:
  text ".Layer_Name" at -23,-1058.49 h60
Top Solder:
  text ".Layer_Name" at -23,-1058.49 h60
  text ".Layer_Name" at -23,-1058.49 h60
Bottom Solder:
  text ".Layer_Name" at -23,-1058.49 h60
Drill Guide:
  text ".Layer_Name" at -23,-1058.49 h60
M1 Board Outline:
  the board outline again, w10
  text ".Layer_Name" at -23,-1058.49 h60
M2 Board Dimensions:
  rectangle: -600,-485.5 -475,-360.5
  rectangle: -475,-610.5 -100,-485.5
  lines w7: -600,-485.5 400,-485.5 ; -475,-610.5 -475,-360.5 ; -350,-610.5 -350,-360.5 ; -100,-610.5 -100,-360.5 ; 150,-610.5 150,-360.5 ; -600,-610.5 400,-610.5 400,-360.5 -600,-360.5 -600,-610.5
  text ".Layer_Name" at -23,-1058.49 h60
M3 3D STEP Top:
  text ".Layer_Name" at -23,-1058.49 h60
M4 3D STEP Bottom:
  text ".Layer_Name" at -23,-1058.49 h60
M5 Assembly Top:
  lines w10: -892,-1130.17 5708,-1130.17 ; -892,-926.83 5710,-926.83 ; -892,-723.5 -892,-1333.5 3113,-1333.5 5710,-1333.5 5710,-723.5 -891.5,-723.5 -891.5,-1333.5 684,-1333.5 ; 1573,-1333.5 1573,-723.5 ; 2840,-926.83 2840,-723.5 ; 3680,-926.83 3680,-723.5 ; 4302,-1340 4302,-1137.17
  text "COMPONENTS MARKED 'DNP' SHOULD NOT BE POPULATED." at 553.5,-518.5 h60
  text "ASSEMBLY VARIANT:" at 553,-634 h60
  text ".VariantName" at 1589,-634 h60
  text "PCB VIEWED FROM TOP SIDE" at -828.5,-855.67 h60
  text "BOARD #:" at 1648,-855.67 h60
  text ".PRJ_Number" at 2193.5,-855.67 h60
  text "REV:" at 3038,-855.67 h60
  text ".PCB_Rev" at 3329.5,-855.67 h60
  text "SVN REV:" at 3876,-855.67 h60
  text ".VersionControl_RevNumber" at 4382,-855.67 h60
  text "IGNORE ->" at -828.5,-1058.49 h60
  text "PLOT NAME =" at -828.5,-1264.34 h60
  text ".plot_File_Name" at -23,-1264.34 h60
  text "GENERATED    :" at 1650,-1264.34 h60
  text ".Print_Date" at 2519.5,-1264.34 h60
  text ".Print_Time" at 3248.5,-1264.34 h60
  text "TEXAS INSTRUMENTS" at 4513,-1264.34 h60
M6 Assembly Bottom:
  lines w10: -892.5,-927.33 5709.5,-927.33 ; -890.5,-1130.67 5709.5,-1130.67 ; 515.5,-1340.5 515.5,-1137.67 ; 1137.5,-927.33 1137.5,-724 ; 1977.5,-927.33 1977.5,-724 ; 3244.5,-1334 3244.5,-724 ; 4133.5,-1334 5709,-1334 5709,-724 -892.5,-724 -892.5,-1334 1704.5,-1334 5709.5,-1334 5709.5,-724
  text "COMPONENTS MARKED 'DNP' SHOULD NOT BE POPULATED." at 6290,-490 h60
  text ".VariantName" at 5246,-606 h60
  text "ASSEMBLY VARIANT:" at 6285,-606 h60
  text ".VersionControl_RevNumber" at 435.5,-856.17 h60
  text "SVN REV:" at 941.5,-856.17 h60
  text ".PCB_Rev" at 1488,-856.17 h60
  text "REV:" at 1779.5,-856.17 h60
  text ".PRJ_Number" at 2624,-856.17 h60
  text "BOARD #:" at 3169.5,-856.17 h60
  text "PCB VIEWED FROM BOTTOM SIDE" at 5646,-856.17 h60
  text "IGNORE ->" at 1947.85,-1058.49 h60
  text "TEXAS INSTRUMENTS" at 304.5,-1264.84 h60
  text ".Print_Time" at 1569,-1264.84 h60
  text ".Print_Date" at 2298,-1264.84 h60
  text "GENERATED    :" at 3167.5,-1264.84 h60
  text ".plot_File_Name" at 4840.5,-1264.84 h60
  text "PLOT NAME =" at 5646,-1264.84 h60
M9 Title Sheet:
  drawing of 57 lines, arcs and shapes, not listed
  text "1" at 139.84,7836.5 h70
  text "2" at 2635.5,7836.5 h70
  text "3" at 5124.84,7836.5 h70
  text "4" at 7631.51,7836.5 h70
  text "5" at 10130.5,7836.5 h70
  text "6" at 12635.5,7836.5 h70
  text "A" at -1016.5,6693.5 h70
  text "A" at 13783.5,6693.5 h70
  text "B" at -1016.5,4313.5 h70
  text "B" at 13783.5,4313.5 h70
  text "C" at -1016.5,1938.5 h70
  text "C" at 13783.5,1938.5 h70
  text "PROJECT TITLE:" at 10743.5,77.5 h45
  text ".PRJ_Title" at 10793.5,-55.83 h70
  text "DESIGNED FOR:" at 10743.5,-223.5 h45
  text ".PRJ_Customer" at 10793.5,-363.5 h70
  text "D" at -1016.5,-431.5 h70
  text "D" at 13783.5,-431.5 h70
  text "FILE NAME:" at 10743.5,-523.5 h45
  text ".PCB_File_Name_No_Path" at 10793.5,-643.5 h70
  text "Texas Instruments (TI) and/or its licensors do not warrant the accuracy or completeness of this specification" at 5774,-805.34 h45
  text "ENGINEER:" at 10743.5,-813.5 h45
  text "LAYOUT BY:" at 12248.5,-813.5 h45
  text "or any information contained therein. TI and/or its licensors do not warrant that this design will meet" at 5729.01,-918 h45
  text ".PRJ_Engineer" at 10793.5,-968.49 h70
  text ".PCB_Layout" at 12299,-968.49 h70
  text "the specifications, will be suitable for your application or fit for any particular purpose, or will operate in" at 5729.01,-1030.67 h45
  text ".Layer_Name" at -23,-1058.49 h60
  text "ALTIUM DESIGNER VERSION:" at 12248.5,-1123.5 h45
  text "an implementation. TI and/or its licensors do not warrant that the design is production worthy. You should" at 5729.01,-1143.33 h45
  text "completely validate and test your design implementation to confirm the system functionality for your application." at 5774,-1256 h45
  text ".print_Scale" at 10793.5,-1256.83 h70
  text ".Application_BuildNumber" at 12299,-1256.83 h70
  text "1" at 139.84,-1463.5 h70
  text "2" at 2635.5,-1463.5 h70
  text "3" at 5124.84,-1463.5 h70
  text "4" at 7631.51,-1463.5 h70
  text "5" at 10130.5,-1463.5 h70
  text "6" at 12635.5,-1463.5 h70
M10 Fab Notes:
  drawing of 185 lines, arcs and shapes, not listed
  text "DESIGN INFORMATION" at 11781.02,5710 h60
  text "MIN. TRACK WIDTH:" at 11136.46,5530 h60
  text "8" at 12232.7,5530 h60
  text "MIL" at 12387.46,5530 h60
  text "MIN. CLEARANCE:" at 11136.46,5398 h60
  text "0.18" at 12149,5398 h60
  text "mm" at 12387.46,5398 h60
  text "MIN. VIA PAD SIZE:" at 11136.46,5266 h60
  text "20" at 12202.71,5266 h60
  text "MIL" at 12387.46,5266 h60
  text "0.127mm (5MIL)" at 11831.46,5124.29 h60
  text "MINIMUM ANNULAR RING" at 10807.23,5120 h60
  text "EXTERNAL" at 12539.46,5120 h60
  text "PER" at 11007.23,5002 h60
  text "IPC-D-275 CLASS 2 LEVEL C" at 11227.23,5002 h60
  text "MIL, HOLES" at 12715.46,4889.71 h60
  text "+/-" at 12323,4889 h60
  text "+/-" at 13177,4889 h60
  text "REGISTRATION TOLERANCES:" at 10807.23,4884 h60
  text "METAL" at 12007,4884 h60
  text "5" at 12583.2,4884 h60
  text "3" at 13416.2,4884 h60
  text "MIL" at 13532.46,4884 h60
  text "MATERIAL:" at 10732.46,4674.54 h60
  text "FR-4 High Tg" at 11718.9,4534.21 h60
  text "FR-408" at 11153.46,4525.64 h60
  text "X" at 11565.46,4525.64 h60
  text "OTHER" at 12641.46,4525.64 h60
  text "62 MIL (1.6mm) +/-10%" at 11473.56,4362.92 h60
  text "THICKNESS:" at 10807.23,4358.64 h60
  text "X" at 11345.4,4358.64 h60
  text "OTHER" at 12758.46,4358.64 h60
  text "TOLERANCE:" at 10807.23,4200.64 h60
  text "X" at 11646.53,4200.64 h60
  text "ANSI IPC-6012 TYPE 3 CLASS 2" at 11833.48,4200.64 h60
  text "OTHER +/-" at 11833.46,4044.64 h60
  text "BOW & TWIST:" at 10807.23,3887.64 h60
  text "X" at 11646.53,3887.64 h60
  text "ANSI IPC-6012 TYPE 3 CLASS 2" at 11833.48,3887.64 h60
  text "OTHER +/-" at 11833.46,3729.13 h60
  text "DRILLING:" at 10732.46,3590.64 h60
  text "REFERENCE:" at 10807.23,3473.64 h60
  text "X" at 11455.46,3473.64 h60
  text "AS SHOWN" at 11642.46,3473.64 h60
  text "X" at 12356.46,3473.64 h60
  text "NC_DRILL FILES" at 12493.46,3473.64 h60
  text "PTH MIN COPPER THICKNESS:" at 10807.23,3315.64 h60
  text "X" at 12157.46,3315.64 h60
  text "1MIL" at 12294.46,3315.64 h60
  text "OTHER" at 12791.46,3315.64 h60
  text "BOARD FINISH:" at 10732.46,3156.64 h60
  text "SILKSCREEN:" at 10887.68,3038.64 h60
  text "X" at 11836.46,3038.64 h60
  text "TOP" at 11962.46,3038.64 h60
  text "X" at 12346.46,3038.64 h60
  text "BOTTOM" at 12473.46,3038.64 h60
  text "SILKSCREEN COLOR:" at 10887.68,2871.64 h60
  text "X" at 11835.42,2871.64 h60
  text "WHITE" at 11962.46,2871.64 h60
  text "OTHER" at 12473.46,2871.64 h60
  text "SOLDER RESIST COLOR:" at 10887.68,2701.64 h60
  text "X" at 11455.42,2542.44 h60
  text "GREEN" at 11582.46,2542.44 h60
  text "BLUE" at 12173.46,2542.44 h60
  text "OTHER" at 12711.46,2542.44 h60
  text "IMMERSION GOLD (ENIG)" at 11793.46,2353.92 h60
  text "ENEPIG" at 13131,2350.64 h60
  text "SURFACE FINISH:" at 10732.46,2349.64 h60
  text "IMM. TIN/SILVER OR EQUIV" at 11062,2192.64 h60
  text "OTHER" at 12493.46,2192.64 h60
  text "X" at 10892,2190 h60
  text "X" at 11603,2016 h60
  text "ARRAY/PANEL:" at 10732.46,2013.64 h60
  text "CUT AND TRIM PER MECH LAYER 1" at 11793.46,2009.35 h60
  text "N.C. ROUTE" at 11793.46,1857.64 h60
  text "V. SCORE" at 12659.46,1857.64 h60
  text "CERTIFICATION:" at 10732.46,1720.64 h60
  text "MATERIALS AND WORKMANSHIP FOR ALL PCBS" at 11457.46,1720.64 h60
  text "TO MEET OR EXCEED THE REQUIREMENTS OF:" at 11457.46,1622.64 h60
  text "X" at 11083.96,1486.13 h60
  text "ANSI IPC-A-600F CLASS ->" at 11222.96,1486.13 h60
  text "X" at 12862.02,1486.13 h60
  text "2" at 12980.96,1486.14 h60
  text "1" at 12665.96,1484.64 h60
  text "3" at 13334.96,1484.64 h60
  text "X" at 11086.02,1326.64 h60
  text "UL 94V-0" at 11222.96,1326.64 h60
  text "X" at 11898.02,1326.64 h60
  text "RoHS" at 12034.96,1326.64 h60
  text "OTHER" at 12679.36,1326.64 h60
  text "PER ORDER" at 13076.42,1326.64 h60
  text "ADDITIONAL REQUIREMENTS:" at 10732.46,1185.64 h60
  text "MICROSECTION:" at 10807.23,1070.64 h60
  text "YES" at 11712.96,1070.64 h60
  text "REQUIRED" at 12574.46,914.49 h60
  text "BARE BOARD ELEC. TEST:" at 10807.23,911.64 h60
  text "NONE" at 12112.96,911.64 h60
  text "X" at 12447.46,911.64 h60
  text "PER ORDER" at 13166.46,911.64 h60
  text "MANUFACTURER'S UL:" at 10807.23,754.64 h60
  text "RAIL" at 11972.96,750.35 h60
  text "METAL" at 12464.77,750.35 h60
  text "X" at 12840,750 h60
  text "SILK" at 12976.46,750.35 h60
  text ".Layer_Name" at -23,-1058.49 h60
M11 Gerber Information:
  lines w10: -892,-1130.17 5708,-1130.17 ; -892,-926.83 5710,-926.83 ; -892,-723.5 -892,-1333.5 3113,-1333.5 5710,-1333.5 5710,-723.5 -891.5,-723.5 -891.5,-1333.5 684,-1333.5 ; 1573,-1333.5 1573,-723.5 ; 2840,-926.83 2840,-723.5 ; 3680,-926.83 3680,-723.5 ; 4302,-1340 4302,-1137.17
  text "ALL ARTWORK VIEWED FROM TOP SIDE" at -828.5,-855.67 h60
  text "BOARD #:" at 1648,-855.67 h60
  text ".PRJ_Number" at 2193.5,-855.67 h60
  text "REV:" at 3038,-855.67 h60
  text ".PCB_Rev" at 3329.5,-855.67 h60
  text "SVN REV:" at 3876,-855.67 h60
  text ".VersionControl_RevNumber" at 4382,-855.67 h60
  text "LAYER NAME =" at -828.5,-1058.49 h60
  text "PLOT NAME =" at -828.5,-1264.34 h60
  text ".plot_File_Name" at -23,-1264.34 h60
  text "GENERATED    :" at 1650,-1264.34 h60
  text ".Print_Date" at 2519.5,-1264.34 h60
  text ".Print_Time" at 3248.5,-1264.34 h60
  text "TEXAS INSTRUMENTS" at 4513,-1264.34 h60
M12 Stackup:
  lines w6: 10760,7260 13310,7260 ; 10760,7364.4 13310,7364.4 ; 10700,6775 ccw(c10734,6775) 10734,6741 13336,6741 ccw(c13336,6775) 13370,6775 13370,7481 ccw(c13336,7481) 13336,7515 10734,7515 ccw(c10734,7481) 10700,7481 10700,6775
  text "Layer Stack Up Detail for: Ref_Design.PcbDoc" at 10760,7397.1 h57
  text "Layer" at 10760,7325.4 h24
  text "Gerber" at 11655.81,7325.4 h24
  text "Copper" at 12219.33,7325.4 h24
  text "Dielectric" at 12822.04,7325.4 h24
  text "Name" at 10760,7277.4 h24
  text "Document" at 11655.81,7277.4 h24
  text "Thickness" at 12219.33,7277.4 h24
  text "Material" at 12822.04,7277.4 h24
  text "Top Solder Mask" at 10760,7184.44 h34
  text "(.GTS)" at 11655.81,7184.44 h34
  text "Solder Resist" at 12822.04,7184.44 h34
  text "Top Layer" at 10760,7087.69 h34
  text "(.GTL)" at 11655.81,7087.69 h34
  text "1.4mil" at 12219.33,7087.69 h34
  text "FR-4" at 12822.04,7039.31 h34
  text "Bottom Layer" at 10760,6990.94 h34
  text "(.GBL)" at 11655.81,6990.94 h34
  text "1.4mil" at 12219.33,6990.94 h34
  text "Bottom Solder Mask" at 10760,6894.19 h34
  text "(.GBS)" at 11655.81,6894.19 h34
  text "Solder Resist" at 12822.04,6894.19 h34
  text ".Layer_Name" at -23,-1058.49 h60
M13 Component Bodies Top:
  text ".Layer_Name" at -23,-1058.49 h60
M14 Component Bodies Bottom:
  text ".Layer_Name" at -23,-1058.49 h60
M15 Courtyards Top:
  text ".Layer_Name" at -23,-1058.49 h60
M16 Courtyards Bottom:
  text ".Layer_Name" at -23,-1058.49 h60
Drill Drawing:
  text ".legend" at 4522.5,525.5 h60
  text "Drill Table" at 4547.5,340.5 h60
  text ".Layer_Name" at -23,-1058.49 h60

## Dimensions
0,0 to 0,2300 on M2 Board Dimensions
0,0 to 3700,0 on M2 Board Dimensions
-600,-610.5 to 400,-610.5 on M2 Board Dimensions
